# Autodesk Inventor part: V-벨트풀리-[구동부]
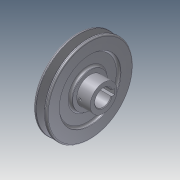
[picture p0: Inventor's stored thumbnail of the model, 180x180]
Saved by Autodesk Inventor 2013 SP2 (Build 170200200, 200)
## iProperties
Company: 한국ATC센터
Created: 2014-10
Part Number: V-벨트풀리-[구동부]
Document SubType Name: Modeling
Designer: 한국ATC센터
Density: 7.86 g/cm^3
Material: 강, 연강
Mass: 1515.01 g
Surface Area: 468.111 cm^2
Volume: 192.75 cm^3
Author: KYOUNG IL JANG
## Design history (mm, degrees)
sketch "스케치1"
  geometry: L1 (-20, 0)-(20, 0); L2 (-20, 0)-(-20, 26); L3 (-20, 26)-(-16, 26); L4 (-16, 26)-(-16, 46); L5 (-16, 46)-(-20, 46); L6 (-20, 46)-(-20, 64.5); L7 (-20, 64.5)-(-16.062, 64.5); L8 (-16.062, 64.5)-(-12.001, 52); L9 (-12.001, 52)-(-7.999, 52); L10 (-7.999, 52)-(-3.938, 64.5); L11 (-3.938, 64.5)-(0, 64.5); L12 (0, 64.5)-(0, 46); L13 (0, 46)-(-4, 46); L14 (-4, 46)-(-4, 26); L15 (-4, 26)-(0, 26); L16 (0, 26)-(0, 20); L17 (0, 20)-(20, 20); L18 (20, 20)-(20, 0); L19 (-14.6, 60)-(-5.4, 60); 2 further points
  constraints: 38 end point, 11 parallel, 7 collinear, 3 equal length, 3 perpendicular, 2 point on line, 1 coincident, 1 horizontal, 1 midpoint
  dimensions: "d0" = 40 distance of L1.start L1.end; "d1" = 4.5 distance between parallel lines of L7 L19; "d2" = 8 distance between parallel lines of L9 L19; "d3" = 9.2 distance of L19.start L19.end; "d4" = 36 deg angle of L10 L8; "d5" = 20 distance between parallel lines of L12 L6; "d6" = 120 diameter of L19 L1; "d7" = 4 distance of L2.end L3.end; "d8" = 52 diameter of L3 L1; "d9" = 92 diameter of L5 L1; "d10" = 40 diameter of L17 L1
revolve "회전1" sketch "스케치1" stored, may be unused: angle "d11" = 90 deg
sketch "스케치2"
  geometry: L1 (-4, 11.843)-(-4, 16.5); L2 (-4, 16.5)-(4, 16.5); L3 (4, 16.5)-(4, 11.843); A1 r 12.5 centre (0, 0) between (-4, 11.843) and (4, 11.843); 1 further point
  constraints: 6 end point, 2 parallel, 2 point on circle, 1 centre point, 1 coincident, 1 horizontal, 1 vertical
  dimensions: "d12" = 25 diameter of A1; "d13" = 8 distance of L1.end L2.end; "d14" = 29 dimension on A1 L2
extrude "돌출1" cut sketch "스케치2" stored distance "d15" = 10; taper "d16" = 0 deg
chamfer "모따기1" distance "d17" = 1; stored, may be unused: second distance "d18" = 2, angle "d19" = 45 deg
node "작업 평면1"
sketch "스케치3"
  geometry: L1 (10, -20)-(10, 20) reference; 3 further points
  constraints: 1 horizontal alignment, 1 midpoint
  dimensions: "d20" = 15 distance from line of L1 point (-5, 0)
hole "구멍1" sketch "스케치3" at (-5, 0) diameter "d21" = 4.459; stored, may be unused: countersink angle "d25" = 90 deg, drill point angle "d27" = 118 deg; dims "d22" = 6, "d23" = 4, "d24" = 2, "d26" = 8
fillet "모깎기1" dims "d28" = 3, "d29" = 2, "d30" = 0.5, "d31" = 1
node "솔리드1"
